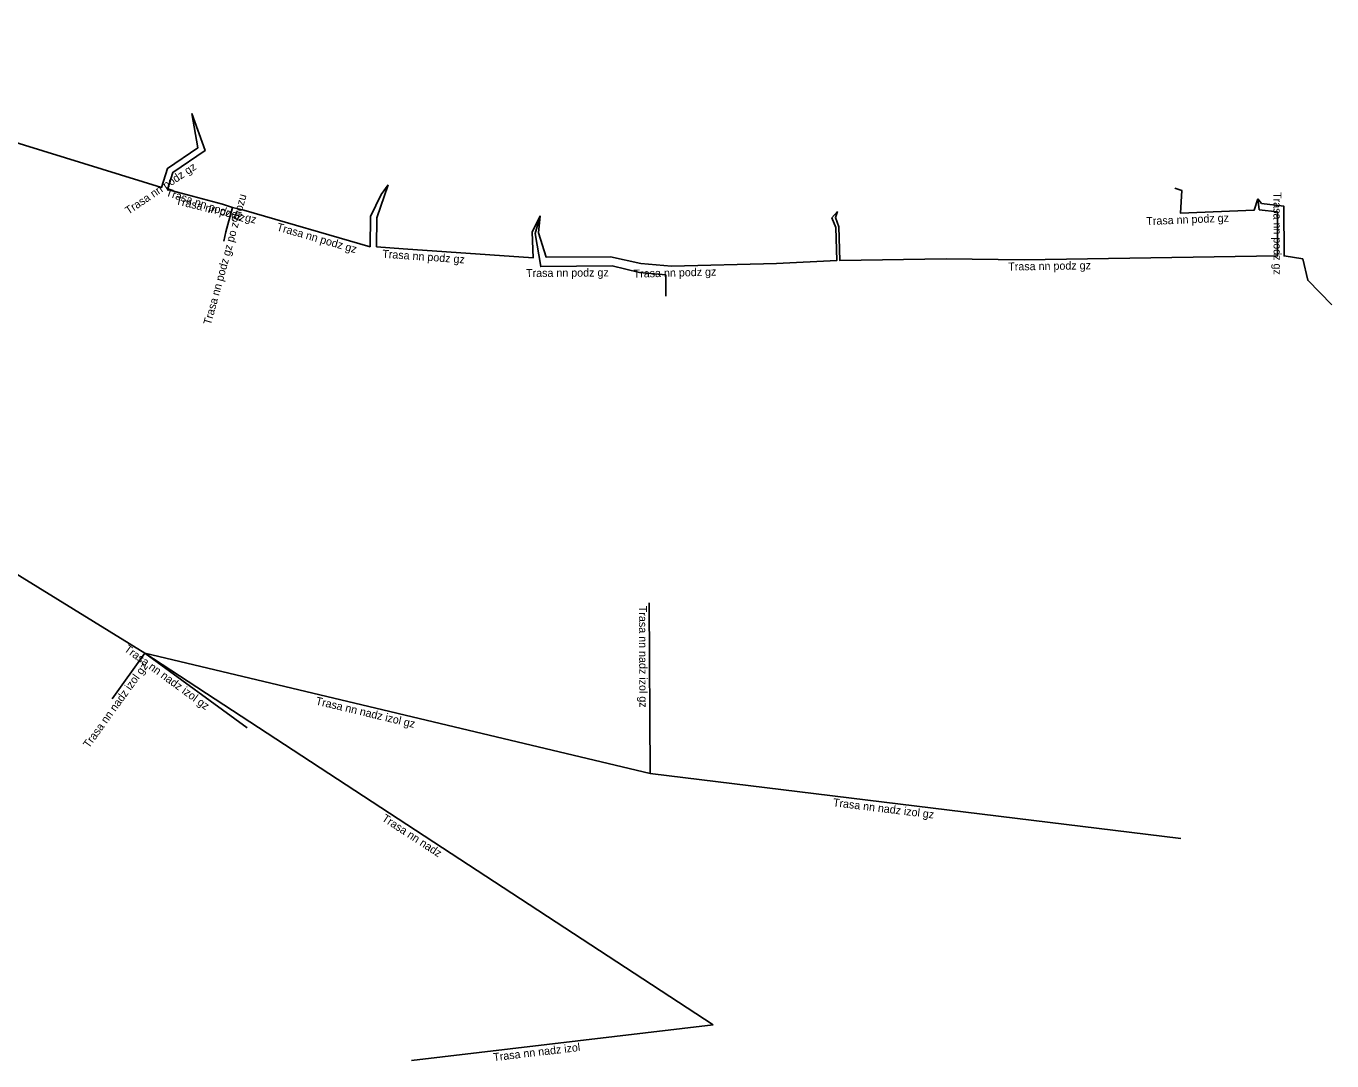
# Model space of a CAD drawing. Extents: x -484846 to -484244, y -1128177 to -1127608.
# Drawn here: x -484325.4 to -484243.8, y -1128177.3 to -1128112.7 of the extents above; entities that cross this region are included whole.
import ezdxf

# ---------------------------------------------------------------- set-up
doc = ezdxf.new("R2010")
doc.units = 0
doc.layers.add('Popiskový text - Ostatní atributy Trasy', color=7, linetype='Continuous')
doc.layers.add('Spojnice NN', color=7, linetype='Continuous')

msp = doc.modelspace()

# ---------------------------------------------------------------- linework, layer by layer
at = {"layer": 'Spojnice NN'}
for points in [[(-484341.155, -1128112.699), (-484339.732, -1128113.198), (-484340.7, -1128116.301), (-484338.28, -1128116.95), (-484337.54, -1128116.72), (-484335.18, -1128117.13), (-484316.906, -1128122.787), (-484316.541, -1128121.584), (-484314.64, -1128120.304), (-484315.01, -1128118.15)], [(-484315.01, -1128118.15), (-484314.18, -1128120.476), (-484316.199, -1128121.836), (-484316.524, -1128122.903), (-484313.09, -1128123.81)], [(-484311.77, -1128124.19), (-484303.87, -1128126.478), (-484303.849, -1128124.582), (-484303.175, -1128123.223), (-484302.753, -1128122.615)], [(-484302.753, -1128122.615), (-484303.451, -1128124.678), (-484303.47, -1128126.482), (-484301.81, -1128126.6), (-484293.68, -1128127.169), (-484293.751, -1128125.566), (-484293.25, -1128124.55)], [(-484253.598, -1128122.823), (-484253.16, -1128122.97), (-484253.24, -1128124.39), (-484248.643, -1128124.192), (-484248.416, -1128123.485)], [(-484313.09, -1128123.81), (-484312.47, -1128124.02)], [(-484313.01, -1128126.14), (-484312.89, -1128125.55), (-484312.47, -1128124.02)], [(-484312.47, -1128124.02), (-484311.77, -1128124.19)], [(-484274.678, -1128124.277), (-484274.81, -1128124.66), (-484274.59, -1128125.24), (-484274.52, -1128127.34), (-484267.88, -1128127.24), (-484263.01, -1128127.3), (-484247.18, -1128127.051), (-484247.189, -1128124.307), (-484248.324, -1128124.173), (-484248.416, -1128123.485)], [(-484248.416, -1128123.485), (-484248.18, -1128123.781), (-484246.791, -1128123.953), (-484246.78, -1128127.049), (-484245.614, -1128127.237), (-484245.294, -1128128.571), (-484243.79, -1128130.1)], [(-484293.25, -1128124.55), (-484293.569, -1128125.655), (-484293.212, -1128127.717), (-484288.744, -1128127.68), (-484287.036, -1128128.092), (-484285.403, -1128128.242), (-484285.401, -1128129.562)], [(-484293.25, -1128124.55), (-484293.349, -1128125.614), (-484292.874, -1128127.136), (-484288.86, -1128127.1), (-484286.96, -1128127.52), (-484285.04, -1128127.7), (-484278.48, -1128127.53), (-484274.72, -1128127.347), (-484274.789, -1128125.28), (-484275.023, -1128124.663), (-484274.678, -1128124.277)], [(-484347.65, -1128133.56), (-484317.94, -1128151.87)], [(-484286.433, -1128148.712), (-484286.38, -1128159.37)], [(-484317.94, -1128151.87), (-484319.987, -1128154.706)], [(-484317.94, -1128151.87), (-484282.448, -1128175.07)], [(-484311.549, -1128156.521), (-484317.94, -1128151.87)], [(-484317.94, -1128151.87), (-484286.38, -1128159.37)], [(-484253.22, -1128163.43), (-484286.38, -1128159.37)], [(-484282.448, -1128175.07), (-484301.29, -1128177.301)]]:
    msp.add_lwpolyline(points, dxfattribs=at)

# ---------------------------------------------------------------- texts
at = {"layer": 'Popiskový text - Ostatní atributy Trasy'}
for s, rotation, p in [('Trasa nn podz gz', 33.96424, (-484318.967, -1128124.485)), ('Trasa nn podz gz', 341.28826, (-484316.676, -1128123.282)), ('Trasa nn podz gz po z?hozu', 74.64986, (-484313.821, -1128131.398)), ('Trasa nn podz gz', 270.20357, (-484247.444, -1128123.069)), ('Trasa nn podz gz', 346.34958, (-484316.057, -1128123.818)), ('Trasa nn podz gz', 2.46629, (-484255.374, -1128125.132)), ('Trasa nn podz gz', 343.84791, (-484309.747, -1128125.453)), ('Trasa nn podz gz', 355.99653, (-484303.126, -1128127.16)), ('Trasa nn podz gz', 0.47446, (-484294.129, -1128128.374)), ('Trasa nn podz gz', 1.48447, (-484287.406, -1128128.412)), ('Trasa nn podz gz', 0.90117, (-484264.005, -1128127.966)), ('Trasa nn nadz izol gz', 270.28089, (-484287.081, -1128148.908)), ('Trasa nn nadz izol gz', 323.95544, (-484319.28, -1128151.699)), ('Trasa nn nadz izol gz', 54.17858, (-484321.442, -1128157.833)), ('Trasa nn nadz izol gz', 346.63141, (-484307.306, -1128155.065)), ('Trasa nn nadz izol gz', 353.01964, (-484274.977, -1128161.421)), ('Trasa nn nadz', 326.82852, (-484303.183, -1128162.292)), ('Trasa nn nadz izol', 6.75103, (-484296.152, -1128177.347))]:
    msp.add_text(s, height=0.5, rotation=rotation, dxfattribs=at).set_placement(p)

doc.saveas('drawing.dxf')
